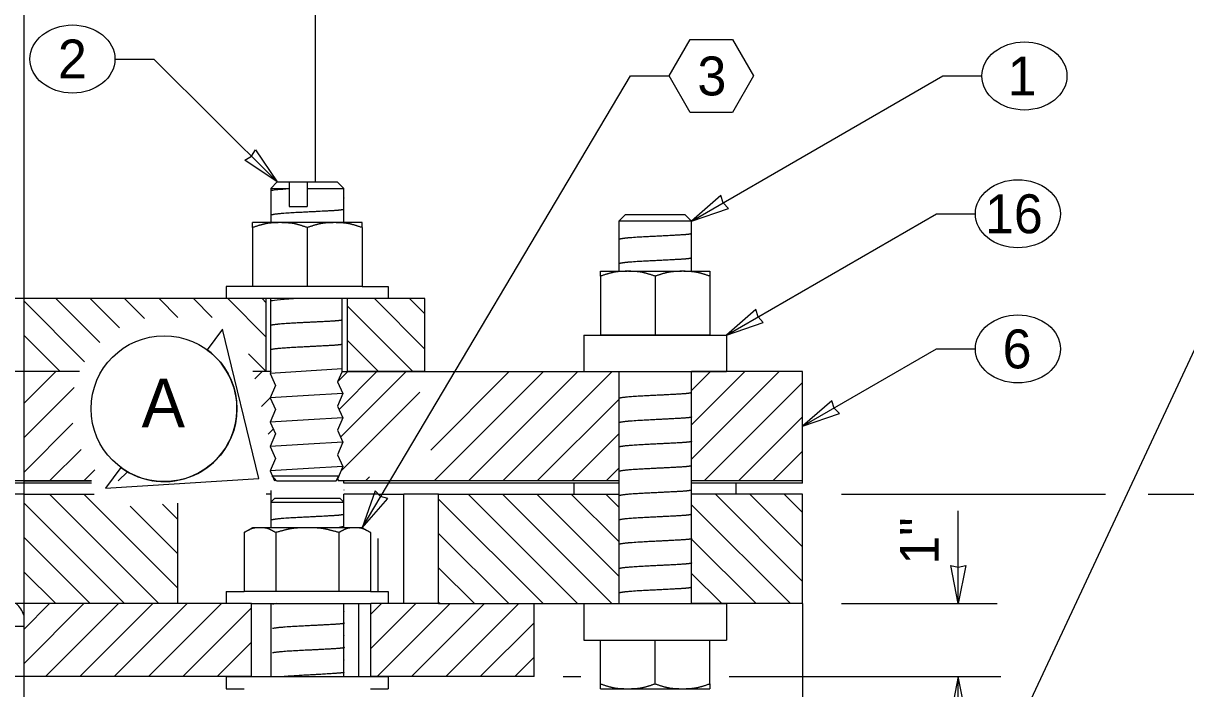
# Model space of a CAD drawing. Extents: x 99862 to 103151, y 100000 to 102076.
# Drawn here: x 101466.5 to 101944.8, y 101497.3 to 101771.1 of the extents above; entities that cross this region are included whole.
import ezdxf

# ---------------------------------------------------------------- set-up
doc = ezdxf.new("R2010")
doc.units = 0
for name, color, linetype in [('Level 15', 7, 'Continuous'), ('Level 2', 7, 'Continuous'), ('Level 20', 7, 'Continuous'), ('Level 3', 7, 'Continuous'), ('Level 4', 7, 'Continuous'), ('Level 6', 7, 'Continuous'), ('Level 62', 7, 'Continuous'), ('Level 7', 7, 'Continuous'), ('Level 9', 7, 'Continuous')]:
    doc.layers.add(name, color=color, linetype=linetype)

msp = doc.modelspace()

# ---------------------------------------------------------------- linework, layer by layer
at = {"layer": 'Level 15'}
for p, q in [((101504.2, 101756.35), (101520.2, 101756.35)), ((101520.2, 101756.35), (101570.98, 101705.78)), ((101605.84, 101563.57), (101716.27, 101749.38)), ((101716.27, 101749.38), (101732.27, 101749.38)), ((101741.47, 101689.67), (101844.89, 101749.38)), ((101844.89, 101749.38), (101860.89, 101749.38)), ((101755.81, 101642.79), (101842.24, 101692.69)), ((101842.24, 101692.69), (101858.24, 101692.69)), ((101853.94, 101434.82), (101971.9, 101687.2)), ((101787.14, 101605.29), (101842.24, 101637.1)), ((101842.24, 101637.1), (101858.24, 101637.1)), ((101803.14, 101577.32), (101911.71, 101577.32)), ((101929.37, 101577.32), (101986.65, 101577.32)), ((101851.14, 101532.32), (101851.14, 101570.52)), ((101803.14, 101532.32), (101867.14, 101532.32)), ((101688.67, 101502.32), (101695.92, 101502.32)), ((101756.91, 101502.32), (101868.67, 101502.32)), ((101851.14, 101470.32), (101851.14, 101502.32))]:
    msp.add_line(p, q, dxfattribs=at)
for points in [[(101570.98, 101705.78), (101557.66, 101714.69), (101560.35, 101716.36), (101562.01, 101719.06)], [(101741.47, 101689.67), (101756.63, 101694.86), (101754.45, 101697.17), (101753.54, 101700.2)], [(101755.81, 101642.79), (101770.97, 101647.98), (101768.8, 101650.29), (101767.89, 101653.32)], [(101787.14, 101605.29), (101802.3, 101610.48), (101800.13, 101612.79), (101799.22, 101615.82)], [(101605.84, 101563.57), (101616.53, 101575.51), (101613.5, 101576.46), (101611.22, 101578.67)], [(101851.14, 101532.32), (101848.06, 101548.05), (101851.14, 101547.32), (101854.23, 101548.05)], [(101851.14, 101502.32), (101848.06, 101486.6), (101851.14, 101487.33), (101854.23, 101486.6)]]:
    msp.add_lwpolyline(points, close=True, dxfattribs=at)
at = {"layer": 'Level 2'}
for p, q in [((101494.53, 101582.79), (101215.52, 101582.79)), ((101711.47, 101582.79), (101598.34, 101582.79)), ((101787.1, 101582.79), (101741.47, 101582.79)), ((101787.1, 101581.85), (101787.1, 101582.79)), ((101466.67, 101581.85), (101146.24, 101581.85)), ((101494.51, 101581.85), (101466.67, 101581.85)), ((101711.47, 101581.85), (101598.33, 101581.85)), ((101787.1, 101581.85), (101741.47, 101581.85))]:
    msp.add_line(p, q, dxfattribs=at)
at = {"layer": 'Level 20'}
for p, q in [((101548.44, 101645.23), (101542.16, 101636.68)), ((101563.45, 101583.81), (101548.44, 101645.23)), ((101506.64, 101588.33), (101500.36, 101579.79)), ((101500.36, 101579.79), (101563.45, 101583.81))]:
    msp.add_line(p, q, dxfattribs=at)
msp.add_lwpolyline([(101732.27, 101749.38), (101740.93, 101764.38), (101758.25, 101764.38), (101766.9, 101749.38), (101758.25, 101734.39), (101740.93, 101734.39), (101732.27, 101749.38)], dxfattribs=at)
msp.add_circle((101524.4, 101612.51), 30, dxfattribs=at)
msp.add_arc((101524.4, 101612.51), 30, 233.6895, 53.6939, dxfattribs=at)
for centre in [(101486.7, 101756.35), (101878.39, 101749.38), (101875.74, 101692.69), (101875.74, 101637.1)]:
    msp.add_ellipse(centre, major_axis=(-17.5, 0), ratio=0.8, dxfattribs=at)
at = {"layer": 'Level 3'}
for p, q in [((101466.67, 101627.79), (101301.67, 101627.79)), ((101466.67, 101614.61), (101479.85, 101627.79)), ((101489.61, 101627.79), (101466.67, 101627.79)), ((101550.34, 101627.58), (101550.56, 101627.79)), ((101568.34, 101627.79), (101560.94, 101627.79)), ((101561.68, 101624.77), (101564.7, 101627.79)), ((101568.34, 101627.79), (101567.99, 101627.02)), ((101567.99, 101627.02), (101570.24, 101622.02)), ((101597.63, 101627.79), (101595.74, 101623.61)), ((101595.78, 101623.53), (101600.05, 101627.79)), ((101596.4, 101612.18), (101612.01, 101627.79)), ((101597.03, 101600.84), (101623.98, 101627.79)), ((101597.63, 101627.79), (101711.47, 101627.79)), ((101634.13, 101595.52), (101666.41, 101627.79)), ((101635.55, 101582.79), (101680.55, 101627.79)), ((101649.69, 101582.79), (101694.69, 101627.79)), ((101663.83, 101582.79), (101708.83, 101627.79)), ((101711.47, 101627.79), (101711.47, 101577.32)), ((101741.47, 101577.32), (101741.47, 101627.79)), ((101787.14, 101627.79), (101741.47, 101627.79)), ((101741.47, 101620.02), (101749.24, 101627.79)), ((101741.47, 101605.88), (101763.38, 101627.79)), ((101741.47, 101591.73), (101777.52, 101627.79)), ((101787.14, 101582.79), (101787.14, 101627.79)), ((101466.67, 101600.47), (101487.41, 101621.22)), ((101570.24, 101622.02), (101567.99, 101617.01)), ((101595.74, 101623.61), (101597.99, 101618.73)), ((101746.67, 101582.79), (101787.14, 101623.27)), ((101564.45, 101613.41), (101568.34, 101617.29)), ((101567.99, 101617.01), (101570.24, 101612.16)), ((101597.99, 101618.73), (101595.74, 101613.6)), ((101597.15, 101586.82), (101629.69, 101619.36)), ((101677.97, 101582.79), (101711.47, 101616.28)), ((101570.24, 101612.16), (101567.99, 101606.99)), ((101595.74, 101613.6), (101597.99, 101608.75)), ((101466.67, 101586.33), (101486.87, 101606.54)), ((101567.99, 101606.99), (101570.24, 101602.14)), ((101597.99, 101608.75), (101595.74, 101603.62)), ((101760.81, 101582.79), (101787.14, 101609.13)), ((101567.23, 101602.04), (101569.32, 101604.13)), ((101570.24, 101602.14), (101567.99, 101597.01)), ((101595.74, 101603.62), (101597.99, 101598.73)), ((101692.12, 101582.79), (101711.47, 101602.14)), ((101567.99, 101597.01), (101570.24, 101592.01)), ((101597.99, 101598.73), (101595.74, 101593.6)), ((101477.27, 101582.79), (101490.27, 101595.79)), ((101570.24, 101592.01), (101567.99, 101587)), ((101595.74, 101593.6), (101597.99, 101588.76)), ((101774.95, 101582.79), (101787.14, 101594.99)), ((101491.41, 101582.79), (101495.95, 101587.32)), ((101597.99, 101588.76), (101595.74, 101583.59)), ((101706.26, 101582.79), (101711.47, 101588)), ((101466.67, 101582.79), (101494.53, 101582.79)), ((101505.56, 101582.79), (101509.33, 101586.57)), ((101519.7, 101582.79), (101519.77, 101582.87)), ((101567.99, 101587), (101569.89, 101582.79)), ((101595.74, 101583.59), (101596.12, 101582.79)), ((101711.47, 101582.79), (101596.12, 101582.79)), ((101607.26, 101582.79), (101608.97, 101584.5)), ((101787.14, 101582.79), (101741.47, 101582.79)), ((101787.1, 101582.79), (101787.14, 101582.79)), ((101466.67, 101577.32), (101495.7, 101577.32)), ((101530.06, 101532.32), (101530.06, 101573.67)), ((101637.35, 101577.32), (101711.47, 101577.32)), ((101637.35, 101532.32), (101637.35, 101577.32)), ((101711.47, 101577.32), (101711.47, 101532.32)), ((101741.47, 101532.32), (101741.47, 101577.32)), ((101787.14, 101577.32), (101741.47, 101577.32)), ((101787.14, 101532.32), (101787.14, 101577.32)), ((101530.06, 101532.32), (101466.67, 101532.32)), ((101637.35, 101532.32), (101711.47, 101532.32)), ((101787.14, 101532.32), (101741.47, 101532.32))]:
    msp.add_line(p, q, dxfattribs=at)
at = {"layer": 'Level 4'}
for p, q in [((101466.67, 101521.7), (101477.29, 101532.32)), ((101466.67, 101507.56), (101491.43, 101532.32)), ((101475.58, 101502.32), (101505.58, 101532.32)), ((101489.72, 101502.32), (101519.72, 101532.32)), ((101503.86, 101502.32), (101533.86, 101532.32)), ((101518, 101502.32), (101548, 101532.32)), ((101560.41, 101532.32), (101530.06, 101532.32)), ((101532.14, 101502.32), (101560.41, 101530.59)), ((101560.41, 101502.32), (101560.41, 101532.32)), ((101604.55, 101502.32), (101604.55, 101532.32)), ((101637.35, 101532.32), (101609.47, 101532.32)), ((101609.47, 101502.32), (101609.47, 101532.32)), ((101609.47, 101527.98), (101613.81, 101532.32)), ((101609.47, 101513.84), (101627.95, 101532.32)), ((101612.09, 101502.32), (101642.09, 101532.32)), ((101626.24, 101502.32), (101656.24, 101532.32)), ((101640.38, 101502.32), (101670.38, 101532.32)), ((101676.67, 101502.32), (101676.67, 101532.32)), ((101654.52, 101502.32), (101676.67, 101524.47)), ((101546.29, 101502.32), (101560.41, 101516.45)), ((101668.66, 101502.32), (101676.67, 101510.33)), ((101466.67, 101502.32), (101256.67, 101502.32)), ((101560.41, 101502.32), (101466.67, 101502.32)), ((101676.67, 101502.32), (101609.47, 101502.32))]:
    msp.add_line(p, q, dxfattribs=at)
at = {"layer": 'Level 6'}
msp.add_line((101787.14, 101532.32), (101787.14, 101457.32), dxfattribs=at)
msp.add_arc((101457.61, 101525.08), 9.4, 15.4311, 50.381, dxfattribs=at)
at = {"layer": 'Level 62'}
for points in [[(101597.63, 101628.86), (101568, 101627.04)], [(101597.99, 101618.73), (101583.78, 101617.98), (101567.99, 101617.01)], [(101597.99, 101608.71), (101583.78, 101607.96), (101567.99, 101606.99)], [(101597.99, 101598.72), (101583.78, 101597.98), (101567.99, 101597.01)], [(101597.99, 101588.71), (101583.78, 101587.97), (101567.99, 101587)]]:
    msp.add_lwpolyline(points, dxfattribs=at)
for points, degree in [([(101575.83, 101702.93), (101571.98, 101702.67), (101569.57, 101702.45), (101568.71, 101702.26)], 3), ([(101598.33, 101699.26), (101598.4, 101699.21), (101598.41, 101699.16), (101598.33, 101699.11)], 3), ([(101597.97, 101694.39), (101597.11, 101694.18), (101595.11, 101694.01), (101592.45, 101693.87), (101582.83, 101693.34), (101571.3, 101692.84), (101568.71, 101692.25)], 4), ([(101598.33, 101689.25), (101598.43, 101689.18), (101598.38, 101689.11), (101598.2, 101689.04)], 3), ([(101741.09, 101684.4), (101740.24, 101684.19), (101738.24, 101684.03), (101735.58, 101683.89), (101725.96, 101683.35), (101714.42, 101682.85), (101711.84, 101682.26)], 4), ([(101741.09, 101674.39), (101740.24, 101674.18), (101738.24, 101674.01), (101735.58, 101673.87), (101725.96, 101673.34), (101714.42, 101672.84), (101711.84, 101672.25)], 4), ([(101579.88, 101657.79), (101573.75, 101657.43), (101569.6, 101657.12), (101568.37, 101656.85)], 3), ([(101597.63, 101648.96), (101596.65, 101648.72), (101594.18, 101648.53), (101590.94, 101648.37), (101581.44, 101647.88), (101570.81, 101647.37), (101568.37, 101646.83)], 4), ([(101597.63, 101638.97), (101596.7, 101638.75), (101594.42, 101638.56), (101591.42, 101638.41), (101581.86, 101637.9), (101570.87, 101637.36), (101568.37, 101636.82)], 4), ([(101741.09, 101618.98), (101740.22, 101618.77), (101738.13, 101618.59), (101735.37, 101618.45), (101725.75, 101617.92), (101714.38, 101617.42), (101711.84, 101616.86)], 4), ([(101741.46, 101609.11), (101741.06, 101608.86), (101738.93, 101608.65), (101735.82, 101608.49), (101726.2, 101607.95), (101714.51, 101607.42), (101711.84, 101606.85)], 4), ([(101741.46, 101599.1), (101741.02, 101598.82), (101738.61, 101598.59), (101735.13, 101598.41), (101725.53, 101597.89), (101714.34, 101597.39), (101711.84, 101596.83)], 4), ([(101741.09, 101588.94), (101740.11, 101588.71), (101737.65, 101588.52), (101734.41, 101588.36), (101724.9, 101587.87), (101714.27, 101587.36), (101711.84, 101586.82)], 4), ([(101598.33, 101579.21), (101598.39, 101579.16), (101598.39, 101579.12), (101598.33, 101579.07)], 3), ([(101741.09, 101578.93), (101740.11, 101578.69), (101737.65, 101578.5), (101734.41, 101578.34), (101724.9, 101577.85), (101714.27, 101577.34), (101711.84, 101576.81)], 4), ([(101597.97, 101568.92), (101597.11, 101568.71), (101595.11, 101568.55), (101592.45, 101568.41), (101582.83, 101567.87), (101571.3, 101567.37), (101568.71, 101566.78)], 4), ([(101741.09, 101568.94), (101740.22, 101568.72), (101738.13, 101568.55), (101735.37, 101568.41), (101725.75, 101567.88), (101714.38, 101567.38), (101711.84, 101566.82)], 4), ([(101598.33, 101564.2), (101598.69, 101563.95), (101597.27, 101563.75), (101594.65, 101563.57)], 3), ([(101741.46, 101559.07), (101741.06, 101558.82), (101738.93, 101558.61), (101735.82, 101558.45), (101726.2, 101557.91), (101714.51, 101557.38), (101711.84, 101556.81)], 4), ([(101741.46, 101549.06), (101741.02, 101548.78), (101738.61, 101548.55), (101735.13, 101548.36), (101725.53, 101547.85), (101714.34, 101547.35), (101711.84, 101546.79)], 4), ([(101741.09, 101538.92), (101740.24, 101538.71), (101738.24, 101538.54), (101735.58, 101538.4), (101725.96, 101537.87), (101714.42, 101537.37), (101711.84, 101536.78)], 4), ([(101570.77, 101532.32), (101569.96, 101532.24), (101569.4, 101532.16), (101569.07, 101532.09)], 3), ([(101598.33, 101529.2), (101598.4, 101529.15), (101598.4, 101529.11), (101598.33, 101529.06)], 3), ([(101598.69, 101524.34), (101598.29, 101524.08), (101596.16, 101523.88), (101593.05, 101523.72), (101583.44, 101523.18), (101571.74, 101522.64), (101569.07, 101522.08)], 4), ([(101598.33, 101524.19), (101598.38, 101524.15), (101598.38, 101524.11), (101598.33, 101524.07)], 3), ([(101598.33, 101519.21), (101598.4, 101519.16), (101598.4, 101519.12), (101598.33, 101519.07)], 3), ([(101598.69, 101514.33), (101598.26, 101514.05), (101595.84, 101513.82), (101592.36, 101513.63), (101582.77, 101513.12), (101571.58, 101512.62), (101569.07, 101512.06)], 4), ([(101598.33, 101514.2), (101598.4, 101514.15), (101598.4, 101514.11), (101598.33, 101514.06)], 3), ([(101598.33, 101509.19), (101598.4, 101509.14), (101598.4, 101509.09), (101598.33, 101509.05)], 3), ([(101598.33, 101504.19), (101598.61, 101503.99), (101597.69, 101503.83), (101595.93, 101503.7), (101590.9, 101503.31), (101581.49, 101502.86), (101573.82, 101502.32)], 4)]:
    msp.add_open_spline(points, degree=degree, dxfattribs=at)
at = {"layer": 'Level 7'}
for p, q in [((101466.67, 101577.32), (101215.52, 101577.32)), ((101466.67, 101573.75), (101508.1, 101532.32)), ((101477.24, 101577.32), (101522.24, 101532.32)), ((101491.38, 101577.32), (101530.06, 101538.64)), ((101523.72, 101573.26), (101530.06, 101566.93)), ((101612.51, 101577.32), (101598.33, 101577.32)), ((101612.51, 101577.32), (101623.12, 101577.32)), ((101623.12, 101532.32), (101623.12, 101577.32)), ((101637.35, 101577.32), (101623.12, 101577.32)), ((101637.35, 101575.37), (101680.4, 101532.32)), ((101649.54, 101577.32), (101694.54, 101532.32)), ((101663.68, 101577.32), (101708.68, 101532.32)), ((101677.83, 101577.32), (101711.47, 101543.68)), ((101691.97, 101577.32), (101711.47, 101557.83)), ((101706.11, 101577.32), (101711.47, 101571.97)), ((101741.47, 101573.02), (101782.17, 101532.32)), ((101751.31, 101577.32), (101787.14, 101541.49)), ((101765.45, 101577.32), (101787.14, 101555.63)), ((101779.59, 101577.32), (101787.14, 101569.77)), ((101510.43, 101572.42), (101530.06, 101552.79)), ((101466.67, 101559.61), (101493.95, 101532.32)), ((101612.51, 101537.32), (101612.51, 101559.13)), ((101637.35, 101561.23), (101666.26, 101532.32)), ((101741.47, 101558.88), (101768.02, 101532.32)), ((101466.67, 101545.47), (101479.81, 101532.32)), ((101637.35, 101547.08), (101652.12, 101532.32)), ((101741.47, 101544.74), (101753.88, 101532.32)), ((101466.67, 101532.32), (101247.29, 101532.32)), ((101637.35, 101532.94), (101637.97, 101532.32)), ((101466.67, 101522.95), (101256.67, 101522.95))]:
    msp.add_line(p, q, dxfattribs=at)
at = {"layer": 'Level 9'}
for p, q in [((101466.67, 101869.87), (101466.67, 101263.31)), ((101586.67, 101705.78), (101586.67, 101837.79)), ((101570.98, 101705.78), (101568.33, 101703.13)), ((101568.33, 101703.13), (101568.33, 101689.04)), ((101568.33, 101703.13), (101575.83, 101703.13)), ((101570.98, 101705.78), (101586.67, 101705.78)), ((101575.83, 101705.78), (101575.83, 101695.63)), ((101583.33, 101705.78), (101583.33, 101695.63)), ((101583.33, 101703.13), (101598.33, 101703.13)), ((101586.67, 101705.78), (101595.68, 101705.78)), ((101598.33, 101703.13), (101595.68, 101705.78)), ((101598.33, 101689.04), (101598.33, 101703.13)), ((101575.83, 101695.63), (101583.33, 101695.63)), ((101598.33, 101689.04), (101560.85, 101689.04)), ((101572.63, 101689.04), (101571.56, 101689.04)), ((101595, 101689.04), (101594.18, 101689.04)), ((101605.84, 101689.04), (101598.33, 101689.04)), ((101714.12, 101692.32), (101711.47, 101689.67)), ((101741.47, 101689.67), (101711.47, 101689.67)), ((101711.47, 101689.67), (101711.47, 101669.04)), ((101738.81, 101692.32), (101714.12, 101692.32)), ((101741.47, 101689.67), (101738.81, 101692.32)), ((101741.47, 101669.04), (101741.47, 101689.67)), ((101560.85, 101687.04), (101560.85, 101662.79)), ((101583.34, 101687.04), (101583.34, 101662.79)), ((101605.84, 101687.03), (101605.84, 101662.79)), ((101703.98, 101669.04), (101714.97, 101669.04)), ((101715.48, 101669.04), (101714.97, 101669.04)), ((101715.48, 101669.04), (101737.24, 101669.04)), ((101738.2, 101669.04), (101737.24, 101669.04)), ((101738.2, 101669.04), (101748.97, 101669.04)), ((101703.97, 101667.03), (101703.97, 101642.79)), ((101726.47, 101667.03), (101726.47, 101642.79)), ((101748.97, 101667.04), (101748.97, 101642.79)), ((101550.01, 101662.79), (101550.01, 101657.79)), ((101605.84, 101662.79), (101550.01, 101662.79)), ((101605.84, 101662.79), (101616.67, 101662.79)), ((101616.67, 101662.79), (101616.67, 101662.79)), ((101616.67, 101662.79), (101616.67, 101657.79)), ((101466.67, 101657.79), (101383.33, 101657.79)), ((101550.01, 101657.79), (101466.67, 101657.79)), ((101466.67, 101656.87), (101491.69, 101631.85)), ((101479.89, 101657.79), (101497.92, 101639.76)), ((101494.03, 101657.79), (101506.05, 101645.78)), ((101508.18, 101657.79), (101516.33, 101649.64)), ((101522.32, 101657.79), (101530.02, 101650.09)), ((101536.46, 101657.79), (101544.22, 101650.03)), ((101566.47, 101657.79), (101550.01, 101657.79)), ((101550.6, 101657.79), (101566.47, 101641.93)), ((101564.74, 101657.79), (101566.47, 101656.07)), ((101599.84, 101657.79), (101566.47, 101657.79)), ((101566.47, 101627.79), (101566.47, 101657.79)), ((101568.34, 101627.79), (101568.34, 101657.79)), ((101597.63, 101627.79), (101597.63, 101657.79)), ((101599.84, 101627.79), (101599.84, 101657.79)), ((101616.67, 101657.79), (101599.84, 101657.79)), ((101599.84, 101654.76), (101626.81, 101627.79)), ((101610.95, 101657.79), (101631.67, 101637.07)), ((101631.67, 101657.79), (101616.67, 101657.79)), ((101625.4, 101657.79), (101631.67, 101651.52)), ((101631.67, 101627.79), (101631.67, 101657.79)), ((101466.67, 101642.73), (101481.61, 101627.79)), ((101599.84, 101640.61), (101612.66, 101627.79)), ((101697.14, 101642.79), (101697.14, 101627.79)), ((101697.14, 101642.79), (101703.97, 101642.79)), ((101726.47, 101642.79), (101703.97, 101642.79)), ((101703.97, 101642.79), (101748.97, 101642.79)), ((101748.97, 101642.79), (101726.47, 101642.79)), ((101748.97, 101642.79), (101755.81, 101642.79)), ((101755.81, 101642.79), (101755.81, 101627.79)), ((101559.15, 101635.1), (101566.46, 101627.79)), ((101489.61, 101627.79), (101466.67, 101627.79)), ((101566.47, 101627.79), (101560.94, 101627.79)), ((101631.67, 101627.79), (101599.84, 101627.79)), ((101697.14, 101627.79), (101755.81, 101627.79)), ((101568.91, 101584.96), (101596.34, 101584.96)), ((101570.61, 101582.79), (101568.91, 101584.96)), ((101570.61, 101582.79), (101595.17, 101582.79)), ((101595.17, 101582.79), (101596.34, 101584.96)), ((101598.33, 101581.85), (101598.33, 101582.79)), ((101568.33, 101578.92), (101568.33, 101574.02)), ((101693.14, 101577.32), (101693.14, 101581.85)), ((101759.81, 101577.32), (101759.81, 101581.85)), ((101568.33, 101577.32), (101566.47, 101577.32)), ((101569.98, 101575.67), (101568.33, 101574.02)), ((101568.33, 101574.02), (101568.33, 101563.57)), ((101568.33, 101574.02), (101598.33, 101574.02)), ((101569.98, 101575.67), (101596.68, 101575.67)), ((101596.68, 101575.67), (101598.33, 101574.02)), ((101598.33, 101574.02), (101598.33, 101577.32)), ((101598.33, 101563.57), (101598.33, 101574.02)), ((101560.84, 101563.57), (101557.36, 101561.56)), ((101568.33, 101563.57), (101560.84, 101563.57)), ((101564.01, 101563.57), (101563.71, 101563.57)), ((101582.78, 101563.57), (101568.33, 101563.57)), ((101583.9, 101563.57), (101582.78, 101563.57)), ((101598.33, 101563.57), (101583.9, 101563.57)), ((101605.84, 101563.57), (101598.33, 101563.57)), ((101603.13, 101563.57), (101602.51, 101563.57)), ((101609.31, 101561.57), (101605.84, 101563.57)), ((101557.36, 101561.56), (101557.36, 101537.32)), ((101570.35, 101561.57), (101570.35, 101537.32)), ((101596.33, 101561.57), (101596.33, 101537.32)), ((101609.31, 101561.57), (101609.31, 101537.32)), ((101550.01, 101537.32), (101550.01, 101532.32)), ((101550.01, 101537.32), (101557.36, 101537.32)), ((101609.31, 101537.32), (101557.36, 101537.32)), ((101609.31, 101537.32), (101616.67, 101537.32)), ((101616.67, 101537.32), (101616.67, 101532.32)), ((101560.41, 101532.32), (101568.33, 101532.32)), ((101568.33, 101532.32), (101568.33, 101502.32)), ((101568.33, 101532.32), (101598.33, 101532.32)), ((101598.33, 101502.32), (101598.33, 101532.32)), ((101598.33, 101532.32), (101609.47, 101532.32)), ((101697.14, 101532.32), (101697.14, 101517.32)), ((101697.14, 101532.32), (101755.81, 101532.32)), ((101755.81, 101532.32), (101755.81, 101517.32)), ((101697.14, 101517.32), (101703.92, 101517.32)), ((101703.92, 101499.33), (101703.92, 101517.32)), ((101703.92, 101517.32), (101748.91, 101517.32)), ((101726.41, 101499.33), (101726.41, 101517.32)), ((101748.91, 101499.33), (101748.91, 101517.32)), ((101748.91, 101517.32), (101755.81, 101517.32)), ((101550.01, 101502.32), (101550.01, 101497.32)), ((101550.01, 101502.32), (101568.33, 101502.32)), ((101568.33, 101502.32), (101598.33, 101502.32)), ((101598.33, 101502.32), (101616.67, 101502.32)), ((101616.67, 101502.32), (101616.67, 101497.32)), ((101550.01, 101497.32), (101550.01, 101497.32)), ((101550.01, 101497.32), (101557.36, 101497.32)), ((101609.31, 101497.32), (101616.67, 101497.32)), ((101703.92, 101497.33), (101714.63, 101497.33)), ((101714.63, 101497.33), (101715.7, 101497.33)), ((101715.7, 101497.33), (101737.18, 101497.33)), ((101737.18, 101497.33), (101738.14, 101497.33)), ((101738.14, 101497.33), (101748.91, 101497.33)), ((101748.91, 101497.33), (101748.91, 101497.33))]:
    msp.add_line(p, q, dxfattribs=at)
for points, degree in [([(101560.85, 101687.04), (101560.85, 101688.21), (101560.85, 101688.98), (101560.85, 101689.04)], 2), ([(101571.56, 101689.04), (101567.91, 101688.98), (101564.35, 101688.2), (101560.85, 101687.04)], 2), ([(101583.34, 101687.04), (101579.83, 101688.21), (101576.27, 101688.98), (101572.63, 101689.04)], 2), ([(101594.18, 101689.04), (101590.49, 101688.99), (101586.88, 101688.22), (101583.34, 101687.04)], 2), ([(101605.84, 101687.03), (101602.29, 101688.22), (101598.69, 101688.99), (101595, 101689.04)], 2), ([(101605.84, 101689.04), (101605.84, 101689.04), (101605.84, 101689.04), (101605.84, 101689.04)], 2), ([(101605.84, 101687.03), (101605.84, 101688.25), (101605.84, 101689.04), (101605.84, 101689.04)], 2), ([(101703.97, 101667.03), (101703.97, 101668.26), (101703.97, 101669.04), (101703.97, 101669.04), (101703.97, 101669.03), (101703.97, 101669.01)], 3), ([(101714.97, 101669.04), (101711.23, 101669.01), (101707.56, 101668.23), (101703.97, 101667.03)], 2), ([(101726.47, 101667.03), (101722.87, 101668.23), (101719.23, 101669.01), (101715.48, 101669.04)], 2), ([(101737.24, 101669.04), (101733.59, 101668.98), (101729.96, 101668.2), (101726.47, 101667.03)], 2), ([(101748.97, 101667.04), (101745.46, 101668.21), (101741.84, 101668.98), (101738.2, 101669.04)], 2), ([(101748.97, 101669.04), (101748.97, 101668.98), (101748.97, 101668.2), (101748.97, 101667.04)], 2), ([(101563.71, 101563.57), (101561.55, 101563.54), (101559.43, 101562.76), (101557.36, 101561.56)], 2), ([(101570.35, 101561.57), (101568.27, 101562.76), (101566.17, 101563.54), (101564.01, 101563.57)], 2), ([(101582.78, 101563.57), (101578.57, 101563.51), (101574.37, 101562.73), (101570.35, 101561.57)], 2), ([(101596.33, 101561.57), (101592.28, 101562.74), (101588.1, 101563.51), (101583.9, 101563.57)], 2), ([(101602.51, 101563.57), (101600.41, 101563.51), (101598.35, 101562.74), (101596.33, 101561.57)], 2), ([(101609.31, 101561.57), (101607.29, 101562.74), (101605.23, 101563.51), (101603.13, 101563.57)], 2), ([(101703.92, 101497.33), (101703.92, 101497.38), (101703.92, 101498.15), (101703.92, 101499.33)], 2), ([(101703.92, 101499.33), (101707.43, 101498.16), (101710.99, 101497.39), (101714.63, 101497.33)], 2), ([(101715.7, 101497.33), (101719.35, 101497.39), (101722.91, 101498.16), (101726.41, 101499.33)], 2), ([(101726.41, 101499.33), (101729.92, 101498.16), (101733.54, 101497.39), (101737.18, 101497.33)], 2), ([(101738.14, 101497.33), (101741.79, 101497.39), (101745.42, 101498.17), (101748.91, 101499.33)], 2), ([(101748.91, 101499.33), (101748.91, 101498.13), (101748.91, 101497.36), (101748.91, 101497.33)], 2)]:
    msp.add_open_spline(points, degree=degree, dxfattribs=at)

# ---------------------------------------------------------------- texts
at = {"layer": 'Level 20'}
for s, height, p in [('2', 16, (101480.71, 101748.35)), ('3', 16, (101743.85, 101741.38)), ('1', 16, (101871.52, 101741.39)), ('16', 16, (101862.16, 101684.69)), ('6', 16, (101869.43, 101629.1)), ('A', 20, (101515.16, 101604.89))]:
    msp.add_text(s, height=height, dxfattribs=at).set_placement(p)
msp.add_text('1"', height=16, rotation=90, dxfattribs=at).set_placement((101843.14, 101548.32))

doc.saveas('drawing.dxf')
